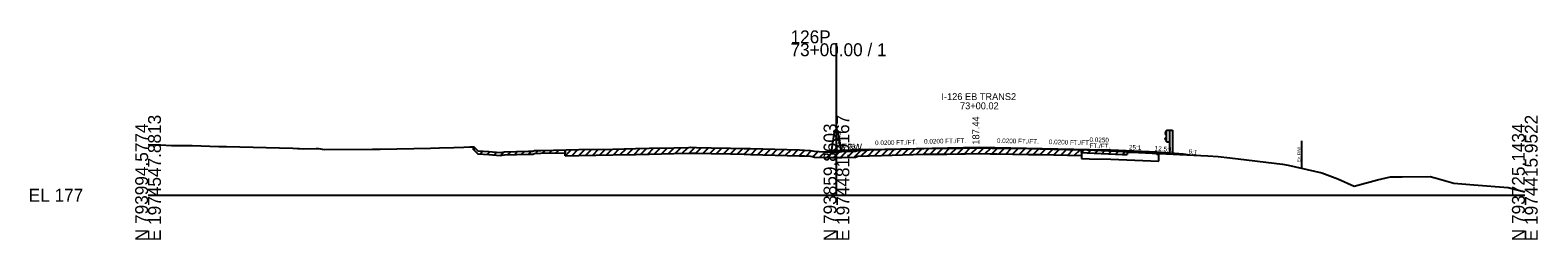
# Model space of a CAD drawing. Extents: x -161 to 1970889, y -4362 to 797231.
# Drawn here: x 2974.3 to 3302.8, y 4990.3 to 5035.9 of the extents above; entities that cross this region are included whole.
import ezdxf

# ---------------------------------------------------------------- set-up
doc = ezdxf.new("R2010")
doc.units = 0
for name, color, linetype in [('RD_GPK_XS_Cell', 7, 'Continuous'), ('RD_XS_Base', 7, 'Continuous'), ('RD_XS_EarthShd', 7, 'Continuous'), ('RD_XS_ExGround', 7, 'Continuous'), ('RD_XS_ExPaveRet', 7, 'Continuous'), ('RD_XS_ExRW', 7, 'Continuous'), ('RD_XS_GR', 7, 'Continuous'), ('RD_XS_MedBWall', 7, 'Continuous'), ('RD_XS_Misc_Line', 7, 'Continuous'), ('RD_XS_Pave', 7, 'Continuous'), ('RD_XS_PaveOvlay', 7, 'Continuous'), ('RD_XS_PaveShd', 7, 'Continuous'), ('RD_XS_TieSlope', 7, 'Continuous'), ('RD_XS_TX_Elev_EX', 7, 'Continuous'), ('RD_XS_TX_Elev_PR', 7, 'Continuous'), ('RD_XS_TX_MkPT', 7, 'Continuous'), ('RD_XS_TX_Profile', 7, 'Continuous'), ('RD_XS_TX_ShdSlope', 7, 'Continuous'), ('RD_XS_TX_Slope', 7, 'Continuous'), ('RD_XS_TX_Station', 7, 'Continuous')]:
    doc.layers.add(name, color=color, linetype=linetype)

msp = doc.modelspace()

# ---------------------------------------------------------------- linework, layer by layer
at = {"layer": 'RD_GPK_XS_Cell'}
for p, q in [((3150, 5000), (3150, 5033.04)), ((3000, 5000), (3150, 5000)), ((3150, 5000), (3300, 5000))]:
    msp.add_line(p, q, dxfattribs=at)
at = {"layer": 'RD_XS_Base'}
for p, q in [((3203.37, 5007.96), (3205.13, 5007.92)), ((3205.13, 5007.92), (3209.78, 5007.81)), ((3209.78, 5007.81), (3220.28, 5007.39)), ((3219.78, 5008.89), (3219.78, 5009.45)), ((3220.28, 5008.87), (3219.78, 5008.89)), ((3220.28, 5007.39), (3220.28, 5008.87))]:
    msp.add_line(p, q, dxfattribs=at)
at = {"layer": 'RD_XS_EarthShd'}
msp.add_line((3219.78, 5009.45), (3221.78, 5009.29), dxfattribs=at)
at = {"layer": 'RD_XS_ExGround'}
msp.add_lwpolyline([(3000, 5011.01), (3002.74, 5010.95), (3005.08, 5010.83), (3009.62, 5010.79), (3015.42, 5010.62), (3015.77, 5010.61), (3016.37, 5010.6), (3017.11, 5010.57), (3031.52, 5010.2), (3032.59, 5010.15), (3033.01, 5010.15), (3033.88, 5010.12), (3036.66, 5010.18), (3037.13, 5010.19), (3038.36, 5009.93), (3048.89, 5009.99), (3049.7, 5010.03), (3050.55, 5010), (3061.56, 5010.24), (3063.51, 5010.31), (3066.6, 5010.38), (3068.84, 5010.45), (3070.14, 5010.49), (3071, 5010.49), (3071.89, 5009.63), (3074.27, 5009.48), (3076.76, 5009.28), (3077.7, 5009.43), (3082.88, 5009.56), (3083.87, 5009.59), (3084.18, 5009.72), (3085.61, 5009.75), (3093.86, 5009.91), (3101.25, 5010.04), (3106.21, 5010.14), (3109.16, 5010.21), (3114.56, 5010.34), (3117.82, 5010.41), (3118.2, 5010.42), (3119.48, 5010.39), (3122.67, 5010.31), (3126.93, 5010.23), (3129.91, 5010.18), (3131.25, 5010.14), (3141.97, 5009.85), (3143.03, 5009.79), (3144.37, 5009.73), (3144.81, 5009.64), (3145.22, 5009.55), (3147.26, 5009.47), (3148.19, 5009.43), (3150, 5009.46), (3150.81, 5009.47), (3151.14, 5009.48), (3154.13, 5009.55), (3154.63, 5009.75), (3156.62, 5009.83), (3157.11, 5009.85), (3159.81, 5009.91), (3169.01, 5010.15), (3174.03, 5010.21), (3177.09, 5010.26), (3178.1, 5010.28), (3180.5, 5010.34), (3183.53, 5010.27), (3183.94, 5010.25), (3184.94, 5010.24), (3191.87, 5010.14), (3194.33, 5010.09), (3204.66, 5009.87), (3212.3, 5009.52), (3213.37, 5009.47), (3213.66, 5009.39), (3214.7, 5009.34), (3215.84, 5009.29), (3226.35, 5008.78), (3230.93, 5008.56), (3233.15, 5008.45), (3235.7, 5008.14), (3247.17, 5006.73), (3248.46, 5006.5), (3255.8, 5004.85), (3259.22, 5003.56), (3262.79, 5001.97), (3267.93, 5003.31), (3270.7, 5004.03), (3273.25, 5004.03), (3279.36, 5004.04), (3281.01, 5003.65), (3284.56, 5002.63), (3288.89, 5002.25), (3296.35, 5001.66), (3300, 5000.75)], dxfattribs=at)
at = {"layer": 'RD_XS_ExPaveRet'}
for p, q in [((3070.89, 5009.87), (3070.89, 5010.49)), ((3070.89, 5009.87), (3071, 5009.87)), ((3071, 5009.87), (3071.89, 5009)), ((3071.89, 5009), (3074.27, 5008.86)), ((3074.27, 5008.86), (3076.76, 5008.66)), ((3076.76, 5008.66), (3077.7, 5008.8)), ((3077.7, 5008.8), (3082.88, 5008.93)), ((3082.88, 5008.93), (3083.87, 5008.96)), ((3083.87, 5008.96), (3084.18, 5009.09)), ((3084.18, 5009.09), (3085.61, 5009.12)), ((3085.61, 5009.12), (3090.89, 5009.23)), ((3090.89, 5008.6), (3090.89, 5009.85)), ((3090.89, 5009.85), (3090.89, 5009.23)), ((3090.89, 5008.6), (3093.86, 5008.66)), ((3093.86, 5008.66), (3101.25, 5008.79)), ((3101.25, 5008.79), (3106.21, 5008.89)), ((3106.21, 5008.89), (3109.16, 5008.96)), ((3109.16, 5008.96), (3114.56, 5009.09)), ((3114.56, 5009.09), (3117.82, 5009.16)), ((3117.82, 5009.16), (3118.2, 5009.17)), ((3118.2, 5009.17), (3119.48, 5009.14)), ((3119.48, 5009.14), (3122.67, 5009.06)), ((3122.67, 5009.06), (3126.93, 5008.98)), ((3126.93, 5008.98), (3129.91, 5008.93)), ((3129.91, 5008.93), (3131.25, 5008.89)), ((3131.25, 5008.89), (3141.97, 5008.6)), ((3141.97, 5008.6), (3143.03, 5008.54)), ((3143.03, 5008.54), (3144.37, 5008.48)), ((3144.37, 5008.48), (3144.81, 5008.39)), ((3144.81, 5008.39), (3145.22, 5008.3)), ((3145.22, 5008.3), (3147.26, 5008.22)), ((3147.26, 5008.22), (3148.19, 5008.18)), ((3148.19, 5008.18), (3150, 5008.21)), ((3150, 5008.21), (3150.81, 5008.22)), ((3150.81, 5008.22), (3151.14, 5008.23)), ((3151.14, 5008.23), (3154.13, 5008.3)), ((3154.13, 5008.3), (3154.63, 5008.5)), ((3154.63, 5008.5), (3156.62, 5008.58)), ((3156.62, 5008.58), (3157.11, 5008.6)), ((3157.11, 5008.6), (3159.81, 5008.66)), ((3159.81, 5008.66), (3169.01, 5008.9)), ((3169.01, 5008.9), (3174.03, 5008.96)), ((3174.03, 5008.96), (3177.09, 5009.01)), ((3177.09, 5009.01), (3178.1, 5009.03)), ((3178.1, 5009.03), (3180.5, 5009.09)), ((3180.5, 5009.09), (3183.53, 5009.02)), ((3183.53, 5009.02), (3183.94, 5009)), ((3183.94, 5009), (3184.94, 5008.99)), ((3184.94, 5008.99), (3191.87, 5008.89)), ((3191.87, 5008.89), (3194.33, 5008.84)), ((3194.33, 5008.84), (3203.37, 5008.65)), ((3203.37, 5009.9), (3203.37, 5008.65)), ((3203.37, 5009.27), (3203.37, 5009.9)), ((3203.37, 5009.27), (3204.66, 5009.24)), ((3204.66, 5009.24), (3212.3, 5008.89)), ((3212.3, 5008.89), (3213.37, 5008.85)), ((3213.37, 5009.47), (3213.37, 5008.85))]:
    msp.add_line(p, q, dxfattribs=at)
at = {"layer": 'RD_XS_ExRW'}
msp.add_line((3251.36, 5011.85), (3251.36, 5005.85), dxfattribs=at)
at = {"layer": 'RD_XS_GR'}
for p, q in [((3221.93, 5014), (3221.65, 5013.56)), ((3221.65, 5013.56), (3221.65, 5013.45)), ((3221.65, 5013.45), (3221.93, 5013.01)), ((3221.93, 5014.16), (3222.59, 5014.16)), ((3221.93, 5011.59), (3221.93, 5014.16)), ((3222.59, 5014.16), (3223.26, 5014.16)), ((3222.59, 5014.16), (3222.59, 5009.22)), ((3223.26, 5014.16), (3223.26, 5009.11)), ((3221.65, 5012.3), (3221.93, 5012.74)), ((3221.65, 5012.19), (3221.65, 5012.3)), ((3221.93, 5011.75), (3221.65, 5012.19)), ((3221.93, 5011.59), (3222.59, 5011.59))]:
    msp.add_line(p, q, dxfattribs=at)
at = {"layer": 'RD_XS_MedBWall'}
for p, q in [((3148.96, 5009.44), (3149.67, 5014.18)), ((3150, 5014.18), (3149.67, 5014.18)), ((3150, 5014.18), (3150.33, 5014.18)), ((3151, 5009.7), (3150.33, 5014.18))]:
    msp.add_line(p, q, dxfattribs=at)
at = {"layer": 'RD_XS_Misc_Line'}
for p, q in [((3070.89, 5009.87), (3071.26, 5010.24)), ((3104.39, 5008.85), (3105.67, 5010.13)), ((3105.89, 5008.88), (3107.17, 5010.16)), ((3107.39, 5008.92), (3108.67, 5010.2)), ((3108.89, 5008.95), (3110.17, 5010.23)), ((3110.39, 5008.99), (3111.67, 5010.27)), ((3111.89, 5009.02), (3113.17, 5010.31)), ((3113.39, 5009.06), (3114.67, 5010.34)), ((3114.89, 5009.1), (3116.17, 5010.37)), ((3116.39, 5009.13), (3117.67, 5010.41)), ((3117.89, 5009.16), (3119.13, 5010.4)), ((3119.39, 5009.14), (3120.61, 5010.36)), ((3120.89, 5009.1), (3122.11, 5010.33)), ((3122.39, 5009.07), (3123.62, 5010.3)), ((3123.89, 5009.04), (3125.12, 5010.27)), ((3125.39, 5009.01), (3126.62, 5010.24)), ((3126.89, 5008.98), (3128.12, 5010.21)), ((3128.39, 5008.96), (3129.62, 5010.18)), ((3129.89, 5008.93), (3131.11, 5010.15)), ((3167.39, 5008.85), (3168.67, 5010.14)), ((3168.89, 5008.89), (3170.16, 5010.16)), ((3170.39, 5008.91), (3171.66, 5010.18)), ((3171.89, 5008.93), (3173.16, 5010.2)), ((3173.39, 5008.95), (3174.66, 5010.22)), ((3174.89, 5008.97), (3176.16, 5010.24)), ((3176.39, 5009), (3177.67, 5010.27)), ((3177.89, 5009.03), (3179.17, 5010.31)), ((3179.39, 5009.06), (3180.66, 5010.34)), ((3180.89, 5009.08), (3182.11, 5010.3)), ((3182.39, 5009.04), (3183.61, 5010.26)), ((3183.89, 5009.01), (3185.12, 5010.24)), ((3185.39, 5008.98), (3186.62, 5010.22)), ((3186.89, 5008.96), (3188.12, 5010.2)), ((3188.39, 5008.94), (3189.62, 5010.17)), ((3189.89, 5008.92), (3191.12, 5010.15)), ((3191.39, 5008.9), (3192.62, 5010.13)), ((3072.39, 5008.97), (3072.98, 5009.56)), ((3073.89, 5008.88), (3074.48, 5009.47)), ((3075.39, 5008.77), (3075.97, 5009.34)), ((3076.89, 5008.68), (3077.63, 5009.42)), ((3078.39, 5008.82), (3079.03, 5009.46)), ((3079.89, 5008.86), (3080.53, 5009.5)), ((3081.39, 5008.9), (3082.03, 5009.54)), ((3082.89, 5008.93), (3083.54, 5009.58)), ((3084.39, 5009.1), (3085.03, 5009.73)), ((3085.89, 5009.13), (3086.53, 5009.76)), ((3087.39, 5009.16), (3088.03, 5009.79)), ((3088.89, 5009.19), (3089.53, 5009.82)), ((3090.89, 5008.6), (3092.17, 5009.88)), ((3092.39, 5008.63), (3093.67, 5009.91)), ((3093.89, 5008.66), (3095.16, 5009.93)), ((3095.39, 5008.69), (3096.66, 5009.96)), ((3096.89, 5008.71), (3098.16, 5009.99)), ((3098.39, 5008.74), (3099.66, 5010.01)), ((3099.89, 5008.77), (3101.16, 5010.04)), ((3101.39, 5008.79), (3102.67, 5010.07)), ((3102.89, 5008.82), (3104.17, 5010.1)), ((3131.39, 5008.89), (3132.61, 5010.11)), ((3132.89, 5008.85), (3134.11, 5010.06)), ((3134.39, 5008.81), (3135.61, 5010.02)), ((3135.89, 5008.76), (3137.11, 5009.98)), ((3137.39, 5008.72), (3138.61, 5009.94)), ((3138.89, 5008.68), (3140.11, 5009.9)), ((3140.39, 5008.64), (3141.61, 5009.86)), ((3141.89, 5008.6), (3143.08, 5009.78)), ((3143.39, 5008.52), (3144.56, 5009.69)), ((3144.89, 5008.37), (3146.04, 5009.52)), ((3146.39, 5008.26), (3147.59, 5009.46)), ((3147.89, 5008.19), (3149.15, 5009.45)), ((3149.39, 5008.2), (3150.66, 5009.47)), ((3150.89, 5008.22), (3152.17, 5009.5)), ((3152.39, 5008.26), (3153.67, 5009.54)), ((3153.89, 5008.3), (3155.37, 5009.78)), ((3155.39, 5008.53), (3156.69, 5009.83)), ((3156.89, 5008.59), (3158.18, 5009.87)), ((3158.39, 5008.63), (3159.67, 5009.91)), ((3159.89, 5008.67), (3161.17, 5009.95)), ((3161.39, 5008.7), (3162.67, 5009.99)), ((3162.89, 5008.74), (3164.17, 5010.02)), ((3164.39, 5008.78), (3165.67, 5010.06)), ((3165.89, 5008.82), (3167.17, 5010.1)), ((3192.89, 5008.87), (3194.12, 5010.09)), ((3194.39, 5008.84), (3195.62, 5010.06)), ((3195.89, 5008.81), (3197.12, 5010.03)), ((3197.39, 5008.77), (3198.62, 5010)), ((3198.89, 5008.74), (3200.12, 5009.97)), ((3200.39, 5008.71), (3201.62, 5009.93)), ((3201.89, 5008.68), (3203.12, 5009.9)), ((3203.37, 5009.27), (3203.98, 5009.88)), ((3204.87, 5009.23), (3205.46, 5009.83)), ((3206.37, 5009.16), (3206.96, 5009.76)), ((3207.87, 5009.1), (3208.46, 5009.69)), ((3209.37, 5009.03), (3209.96, 5009.63)), ((3210.87, 5008.96), (3211.46, 5009.56)), ((3212.37, 5008.89), (3212.96, 5009.49))]:
    msp.add_line(p, q, dxfattribs=at)
at = {"layer": 'RD_XS_Pave'}
for p, q in [((3157.13, 5009.96), (3181.13, 5010.44)), ((3181.13, 5010.44), (3205.13, 5009.96)), ((3205.13, 5009.96), (3209.78, 5009.85))]:
    msp.add_line(p, q, dxfattribs=at)
at = {"layer": 'RD_XS_PaveOvlay'}
for p, q in [((3159.81, 5009.91), (3169.01, 5010.15)), ((3169.01, 5010.15), (3174.03, 5010.21)), ((3174.03, 5010.21), (3177.09, 5010.26)), ((3177.09, 5010.26), (3178.1, 5010.28)), ((3178.1, 5010.28), (3180.5, 5010.34)), ((3180.5, 5010.34), (3183.53, 5010.27)), ((3183.53, 5010.27), (3183.94, 5010.25)), ((3183.94, 5010.25), (3184.94, 5010.24)), ((3184.94, 5010.24), (3191.87, 5010.14)), ((3191.87, 5010.14), (3194.33, 5010.09)), ((3150, 5009.46), (3150.81, 5009.47)), ((3150.81, 5009.47), (3151.14, 5009.48)), ((3151.14, 5009.48), (3154.13, 5009.55)), ((3154.13, 5009.55), (3154.63, 5009.75)), ((3154.63, 5009.75), (3156.62, 5009.83)), ((3156.62, 5009.83), (3157.11, 5009.85)), ((3157.11, 5009.85), (3159.81, 5009.91)), ((3194.33, 5010.09), (3203.37, 5009.9)), ((3203.37, 5009.9), (3203.37, 5007.96))]:
    msp.add_line(p, q, dxfattribs=at)
at = {"layer": 'RD_XS_PaveShd'}
for p, q in [((3157.13, 5009.96), (3148.99, 5009.64)), ((3209.78, 5009.85), (3219.78, 5009.45))]:
    msp.add_line(p, q, dxfattribs=at)
at = {"layer": 'RD_XS_TieSlope'}
for p, q in [((3221.78, 5009.29), (3225.53, 5008.99)), ((3225.53, 5008.99), (3226.99, 5008.75))]:
    msp.add_line(p, q, dxfattribs=at)

# ---------------------------------------------------------------- texts
at = {"layer": 'RD_GPK_XS_Cell'}
for s, p in [('73+00.00 / 1', (3140, 5030.24)), ('126P', (3140, 5033.04)), ('EL 177', (2974, 4998.6))]:
    msp.add_text(s, height=2.8, dxfattribs=at).set_placement(p)
for s, p in [('E 1974547.8813', (3002.8, 4990)), ('E 1974481.9167', (3152.8, 4990)), ('E 1974415.9522', (3302.8, 4990)), ('N 793994.5774', (3000, 4990)), ('N 793859.8603', (3150, 4990)), ('N 793725.1434', (3300, 4990))]:
    msp.add_text(s, height=2.8, rotation=90, dxfattribs=at).set_placement(p)
at = {"layer": 'RD_XS_ExRW'}
msp.add_text('Ex. R/W ', height=0.65, rotation=90, dxfattribs=at).set_placement((3251.11, 5007.23))
at = {"layer": 'RD_XS_TX_Elev_EX'}
msp.add_text('186.46', height=1, rotation=90, dxfattribs=at).set_placement((3151, 5009.46))
at = {"layer": 'RD_XS_TX_Elev_PR'}
msp.add_text(' 187.44', height=1.5, rotation=90, dxfattribs=at).set_placement((3181.13, 5010.44))
at = {"layer": 'RD_XS_TX_MkPT'}
msp.add_text('EBW', height=1.5, dxfattribs=at).set_placement((3151, 5009.7))
at = {"layer": 'RD_XS_TX_Profile'}
for rotation, p in [(2.2906, (3152.5, 5010.03)), (357.7094, (3213.73, 5009.94))]:
    msp.add_text('25:1', height=1, rotation=rotation, dxfattribs=at).set_placement(p)
at = {"layer": 'RD_XS_TX_ShdSlope'}
msp.add_text('12.5:1', height=1, rotation=355.4261, dxfattribs=at).set_placement((3219.32, 5009.73))
at = {"layer": 'RD_XS_TX_Slope'}
for s, rotation, p in [('0.0200 FT./FT.', 1.1458, (3158.43, 5010.88)), ('0.0200 FT./FT.', 1.1452, (3169.11, 5011.2)), ('0.0200 FT./FT.', 358.8537, (3184.96, 5011.37)), ('0.0200 FT./FT.', 358.5681, (3196.28, 5011.12)), ('0.0250', 358.569, (3205.13, 5011.59)), ('FT./FT.', 358.569, (3205.13, 5010.28)), ('6:1', 350.5378, (3226.66, 5009.08))]:
    msp.add_text(s, height=1, rotation=rotation, dxfattribs=at).set_placement(p)
at = {"layer": 'RD_XS_TX_Station'}
for s, p in [('I-126 EB TRANS2', (3172.88, 5020.69)), ('73+00.02', (3176.93, 5018.69))]:
    msp.add_text(s, height=1.5, dxfattribs=at).set_placement(p)

doc.saveas('drawing.dxf')
